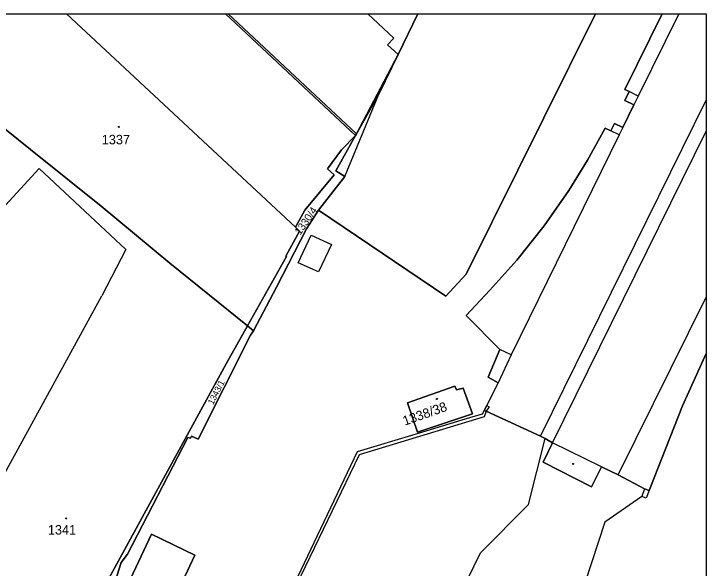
# Model space of a CAD drawing. Extents: x -598934 to -598196, y -1162208 to -1161502.
# Drawn here: x -598319.6 to -598195.6, y -1161604.5 to -1161505.2 of the extents above; entities that cross this region are included whole.
import ezdxf

# ---------------------------------------------------------------- set-up
doc = ezdxf.new("R2010")
doc.units = 0
for name, color, linetype in [('KN_CAR_KR', 7, 'Continuous'), ('KN_KULTURY', 7, 'Continuous'), ('KN_PARC_CIS_POZ', 7, 'Continuous'), ('KN_PARC_CIS_STAV', 7, 'Continuous'), ('KN_PARC_PLOCHA', 7, 'Continuous'), ('parcely_l', 7, 'Continuous')]:
    doc.layers.add(name, color=color, linetype=linetype)

msp = doc.modelspace()

# ---------------------------------------------------------------- linework, layer by layer
at = {"layer": 'KN_CAR_KR'}
for points in [[(-598310.21, -1161505.18), (-598269.13, -1161543.42)], [(-598281.24, -1161505.18), (-598258.2, -1161526.66)], [(-598251.51, -1161509.51), (-598256.16, -1161505.18)], [(-598200.43, -1161505.18), (-598207.74, -1161519.91)], [(-598252.64, -1161510.72), (-598251.51, -1161509.51)], [(-598252.64, -1161510.72), (-598250.78, -1161512.46)], [(-598258.2, -1161526.66), (-598250.78, -1161512.46)], [(-598260.31, -1161534.3), (-598254.22, -1161519.55)], [(-598207.74, -1161519.91), (-598209.37, -1161519.11)], [(-598225.24, -1161580.85), (-598195.56, -1161520.62)], [(-598207.74, -1161519.91), (-598208.52, -1161521.49)], [(-598210.52, -1161525.57), (-598211.16, -1161526.88)], [(-598211.16, -1161526.88), (-598230.52, -1161566.27)], [(-598223.09, -1161582.03), (-598195.56, -1161526.17)], [(-598211.16, -1161526.88), (-598212.65, -1161526.15)], [(-598325.19, -1161543.82), (-598315.06, -1161532.9)], [(-598315.06, -1161532.9), (-598299.54, -1161547.41)], [(-598268.66, -1161549.76), (-598266.33, -1161544.86)], [(-598266.33, -1161544.86), (-598262.7, -1161546.52)], [(-598262.7, -1161546.52), (-598265.02, -1161551.39)], [(-598299.54, -1161547.41), (-598303.83, -1161555.7)], [(-598265.02, -1161551.39), (-598268.66, -1161549.76)], [(-598341.18, -1161623.85), (-598303.83, -1161555.7)], [(-598211.34, -1161587.78), (-598195.56, -1161555.92)], [(-598230.52, -1161566.27), (-598232.55, -1161565.33)], [(-598230.52, -1161566.27), (-598232.81, -1161571.29)], [(-598234.84, -1161575.37), (-598234.47, -1161575.57)], [(-598235.34, -1161576.26), (-598235.68, -1161576.88)], [(-598234.96, -1161576.36), (-598235.35, -1161577.35)], [(-598234.47, -1161575.57), (-598234.96, -1161576.36)], [(-598235.35, -1161577.35), (-598257.74, -1161584.17)], [(-598237.97, -1161577.57), (-598247.74, -1161580.52)], [(-598235.68, -1161576.88), (-598237.97, -1161577.57)], [(-598247.74, -1161580.52), (-598258.12, -1161583.66)], [(-598227.37, -1161593.09), (-598224.4, -1161581.27)], [(-598214.34, -1161586.31), (-598223.09, -1161582.03)], [(-598258.12, -1161583.66), (-598274.19, -1161617.38)], [(-598257.74, -1161584.17), (-598273.86, -1161617.64)], [(-598206.61, -1161590.29), (-598207.06, -1161591.64)], [(-598205.79, -1161590.56), (-598206.32, -1161591.97), (-598207.06, -1161591.64)], [(-598207.06, -1161591.64), (-598213.74, -1161596.25)], [(-598236, -1161601.77), (-598227.37, -1161593.09)], [(-598213.74, -1161596.25), (-598217.31, -1161607.19)], [(-598254.85, -1161640.43), (-598236, -1161601.77)]]:
    msp.add_lwpolyline(points, dxfattribs=at)
at = {"layer": 'KN_KULTURY'}
for centre, radius in [((-598300.83, -1161525.43), 0.09), ((-598300.83, -1161525.43), 0.0398), ((-598243.81, -1161574.18), 0.09), ((-598243.81, -1161574.18), 0.0398), ((-598219.41, -1161585.81), 0.09), ((-598219.41, -1161585.81), 0.0398), ((-598310.23, -1161595.59), 0.09), ((-598310.23, -1161595.59), 0.0398)]:
    msp.add_circle(centre, radius, dxfattribs=at)
at = {"layer": 'KN_PARC_PLOCHA'}
for points in [[(-598258.37, -1161526.97), (-598260.89, -1161529.57), (-598263.39, -1161532.94), (-598262.19, -1161534.05), (-598267.45, -1161540.35), (-598269.13, -1161543.42), (-598268.44, -1161544.09), (-598270.88, -1161548.57), (-598270.76, -1161548.66), (-598277.75, -1161561.08), (-598291.69, -1161549.87), (-598303.99, -1161539.63), (-598316.62, -1161529.5), (-598325, -1161522.8), (-598333.3, -1161514.67), (-598331.51, -1161512.97), (-598322.12, -1161505.18), (-598281.71, -1161505.18), (-598274.21, -1161512.18), (-598265.85, -1161519.99)], [(-598258.37, -1161526.97), (-598265.85, -1161519.99), (-598274.21, -1161512.18), (-598281.71, -1161505.18), (-598247.25, -1161505.18), (-598250.78, -1161512.46), (-598254.22, -1161519.55), (-598258.2, -1161526.66)], [(-598265.01, -1161540.35), (-598260.31, -1161534.3), (-598261.9, -1161533.29), (-598258.37, -1161526.97), (-598258.2, -1161526.66), (-598254.22, -1161519.55), (-598250.78, -1161512.46), (-598247.25, -1161505.18), (-598215.38, -1161505.18), (-598238.54, -1161551.83), (-598242.21, -1161555.73)], [(-598195.56, -1161566.03), (-598199.8, -1161575.39), (-598205.79, -1161590.56), (-598206.61, -1161590.29), (-598211.34, -1161587.78), (-598214.34, -1161586.31), (-598216.09, -1161589.92), (-598224.75, -1161585.47), (-598223.09, -1161582.03), (-598224.4, -1161581.27), (-598225.24, -1161580.85), (-598234.96, -1161576.36), (-598235.34, -1161576.26), (-598234.84, -1161575.37), (-598232.81, -1161571.29), (-598234.65, -1161570.28), (-598232.55, -1161565.33), (-598238.55, -1161559.2), (-598234.35, -1161554.67), (-598229.48, -1161549.32), (-598224.61, -1161543.17), (-598220.18, -1161536.83), (-598216.8, -1161531.4), (-598213.68, -1161525.64), (-598212.65, -1161526.15), (-598212.01, -1161524.84), (-598210.52, -1161525.57), (-598208.52, -1161521.49), (-598210.14, -1161520.69), (-598209.37, -1161519.11), (-598210.16, -1161518.72), (-598203.45, -1161505.18), (-598195.56, -1161505.18)], [(-598277.75, -1161561.08), (-598281.57, -1161567.88), (-598322.97, -1161643.5), (-598335.08, -1161630.46), (-598341.18, -1161623.85), (-598341.89, -1161623.08), (-598366.15, -1161596.79), (-598369.55, -1161593.36), (-598370.8, -1161592.1), (-598388.6, -1161574.13), (-598387.95, -1161573.46), (-598388.28, -1161573.14), (-598383.48, -1161567.99), (-598383.11, -1161568.33), (-598344.06, -1161526.26), (-598344.5, -1161525.85), (-598334.36, -1161514.94), (-598333.97, -1161515.3), (-598333.3, -1161514.67), (-598325, -1161522.8), (-598316.62, -1161529.5), (-598303.99, -1161539.63), (-598291.69, -1161549.87)], [(-598265.01, -1161540.35), (-598267.18, -1161543.72), (-598272.53, -1161554.13), (-598276.66, -1161561.96), (-598277.75, -1161561.08), (-598270.76, -1161548.66), (-598270.88, -1161548.57), (-598268.44, -1161544.09), (-598269.13, -1161543.42), (-598267.45, -1161540.35), (-598262.19, -1161534.05), (-598263.39, -1161532.94), (-598260.89, -1161529.57), (-598258.37, -1161526.97), (-598261.9, -1161533.29), (-598260.31, -1161534.3)], [(-598276.66, -1161561.96), (-598277.2, -1161562.77), (-598286.62, -1161581.38), (-598287.78, -1161580.83), (-598287.97, -1161581.19), (-598288.46, -1161581.06), (-598299.23, -1161601.96), (-598300.37, -1161603.49), (-598303.28, -1161612.54), (-598305.02, -1161616.39), (-598303.48, -1161618.34), (-598302.99, -1161619), (-598303.76, -1161619.55), (-598307.93, -1161623.3), (-598308.55, -1161623.92), (-598308.49, -1161628.62), (-598314.24, -1161648.01), (-598315.37, -1161653.13), (-598323.26, -1161644.05), (-598322.97, -1161643.5), (-598281.57, -1161567.88), (-598277.75, -1161561.08)], [(-598240.61, -1161571.87), (-598240.32, -1161572.56), (-598239.1, -1161572.24), (-598237.45, -1161576.85), (-598247.27, -1161580.15), (-598249.07, -1161574.87)], [(-598240.61, -1161571.87), (-598249.07, -1161574.87), (-598247.27, -1161580.15), (-598237.45, -1161576.85), (-598239.1, -1161572.24), (-598240.32, -1161572.56)], [(-598287.16, -1161602.13), (-598294.61, -1161617.97), (-598302.42, -1161614.31), (-598294.97, -1161598.42)], [(-598287.16, -1161602.13), (-598294.97, -1161598.42), (-598302.42, -1161614.31), (-598294.61, -1161617.97)]]:
    msp.add_lwpolyline(points, close=True, dxfattribs=at)
msp.add_lwpolyline([(-598303.28, -1161612.54), (-598300.37, -1161603.49), (-598299.23, -1161601.96), (-598288.46, -1161581.06), (-598287.97, -1161581.19), (-598287.78, -1161580.83), (-598286.62, -1161581.38), (-598277.2, -1161562.77), (-598276.66, -1161561.96), (-598272.53, -1161554.13), (-598267.18, -1161543.72), (-598265.01, -1161540.35), (-598242.21, -1161555.73), (-598238.54, -1161551.83), (-598215.38, -1161505.18), (-598203.45, -1161505.18), (-598210.16, -1161518.72), (-598209.37, -1161519.11), (-598210.14, -1161520.69), (-598208.52, -1161521.49), (-598210.52, -1161525.57), (-598212.01, -1161524.84), (-598212.65, -1161526.15), (-598213.68, -1161525.64), (-598216.8, -1161531.4), (-598220.18, -1161536.83), (-598224.61, -1161543.17), (-598229.48, -1161549.32), (-598234.35, -1161554.67), (-598238.55, -1161559.2), (-598232.55, -1161565.33), (-598234.65, -1161570.28), (-598232.81, -1161571.29), (-598234.84, -1161575.37), (-598235.34, -1161576.26), (-598234.96, -1161576.36), (-598225.24, -1161580.85), (-598224.4, -1161581.27), (-598223.09, -1161582.03), (-598224.75, -1161585.47), (-598216.09, -1161589.92), (-598214.34, -1161586.31), (-598211.34, -1161587.78), (-598206.61, -1161590.29), (-598205.79, -1161590.56), (-598199.8, -1161575.39), (-598195.56, -1161566.03), (-598195.56, -1161700.65)], dxfattribs=at)
at = {"layer": 'parcely_l'}
for points in [[(-598322.12, -1161505.18), (-598281.71, -1161505.18)], [(-598258.37, -1161526.97), (-598265.85, -1161519.99), (-598274.21, -1161512.18), (-598281.71, -1161505.18)], [(-598281.71, -1161505.18), (-598247.25, -1161505.18)], [(-598265.01, -1161540.35), (-598242.21, -1161555.73), (-598238.54, -1161551.83), (-598215.38, -1161505.18)], [(-598258.37, -1161526.97), (-598258.2, -1161526.66), (-598254.22, -1161519.55), (-598250.78, -1161512.46), (-598247.25, -1161505.18)], [(-598247.25, -1161505.18), (-598215.38, -1161505.18)], [(-598203.45, -1161505.18), (-598210.16, -1161518.72), (-598209.37, -1161519.11), (-598210.14, -1161520.69), (-598208.52, -1161521.49), (-598210.52, -1161525.57), (-598212.01, -1161524.84), (-598212.65, -1161526.15), (-598213.68, -1161525.64), (-598216.8, -1161531.4), (-598220.18, -1161536.83), (-598224.61, -1161543.17), (-598229.48, -1161549.32), (-598234.35, -1161554.67), (-598238.55, -1161559.2), (-598232.55, -1161565.33), (-598234.65, -1161570.28), (-598232.81, -1161571.29), (-598234.84, -1161575.37), (-598235.34, -1161576.26), (-598234.96, -1161576.36), (-598225.24, -1161580.85), (-598224.4, -1161581.27), (-598223.09, -1161582.03), (-598224.75, -1161585.47), (-598216.09, -1161589.92), (-598214.34, -1161586.31), (-598211.34, -1161587.78), (-598206.61, -1161590.29), (-598205.79, -1161590.56), (-598199.8, -1161575.39), (-598195.56, -1161566.03)], [(-598215.38, -1161505.18), (-598203.45, -1161505.18)], [(-598203.45, -1161505.18), (-598195.56, -1161505.18), (-598195.56, -1161566.03)], [(-598277.75, -1161561.08), (-598291.69, -1161549.87), (-598303.99, -1161539.63), (-598316.62, -1161529.5), (-598325, -1161522.8), (-598333.3, -1161514.67)], [(-598277.75, -1161561.08), (-598270.76, -1161548.66), (-598270.88, -1161548.57), (-598268.44, -1161544.09), (-598269.13, -1161543.42), (-598267.45, -1161540.35), (-598262.19, -1161534.05), (-598263.39, -1161532.94), (-598260.89, -1161529.57), (-598258.37, -1161526.97)], [(-598265.01, -1161540.35), (-598260.31, -1161534.3), (-598261.9, -1161533.29), (-598258.37, -1161526.97)], [(-598276.66, -1161561.96), (-598272.53, -1161554.13), (-598267.18, -1161543.72), (-598265.01, -1161540.35)], [(-598322.97, -1161643.5), (-598281.57, -1161567.88), (-598277.75, -1161561.08)], [(-598277.75, -1161561.08), (-598276.66, -1161561.96)], [(-598315.37, -1161653.13), (-598314.24, -1161648.01), (-598308.49, -1161628.62), (-598308.55, -1161623.92), (-598307.93, -1161623.3), (-598303.76, -1161619.55), (-598302.99, -1161619), (-598303.48, -1161618.34), (-598305.02, -1161616.39), (-598303.28, -1161612.54), (-598300.37, -1161603.49), (-598299.23, -1161601.96), (-598288.46, -1161581.06), (-598287.97, -1161581.19), (-598287.78, -1161580.83), (-598286.62, -1161581.38), (-598277.2, -1161562.77), (-598276.66, -1161561.96)], [(-598195.56, -1161566.03), (-598195.56, -1161700.65)], [(-598240.61, -1161571.87), (-598249.07, -1161574.87), (-598247.27, -1161580.15), (-598237.45, -1161576.85), (-598239.1, -1161572.24), (-598240.32, -1161572.56), (-598240.61, -1161571.87)], [(-598287.16, -1161602.13), (-598294.97, -1161598.42), (-598302.42, -1161614.31), (-598294.61, -1161617.97), (-598287.16, -1161602.13)]]:
    msp.add_lwpolyline(points, dxfattribs=at)

# ---------------------------------------------------------------- texts
at = {"layer": 'KN_PARC_CIS_POZ'}
for s, height, rotation, p in [('1330/4', 1.35, 55.2991, (-598268.31, -1161544.91)), ('1343/1', 1.14, 62.8011, (-598283.92, -1161575.32))]:
    msp.add_text(s, height=height, rotation=rotation, dxfattribs=at).set_placement(p)
at = {"layer": 'KN_PARC_CIS_STAV'}
for s, p in [('1337', (-598303.86, -1161528.56)), ('1341', (-598313.52, -1161598.47))]:
    msp.add_text(s, height=1.7, dxfattribs=at).set_placement(p)
msp.add_text('1338/38', height=1.7, rotation=19.4806, dxfattribs=at).set_placement((-598249.58, -1161578.98))

doc.saveas('drawing.dxf')
